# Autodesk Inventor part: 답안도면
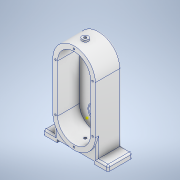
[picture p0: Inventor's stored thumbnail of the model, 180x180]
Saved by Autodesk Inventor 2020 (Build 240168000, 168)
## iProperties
Created: 2021-05
Part Number: 답안도면
Material: 알루미늄 6061
Document SubType Name: Modeling
Designer: OWner
Density: 2.7 g/cm^3
Appearance: 알루미늄 - 평지
Author: OWner
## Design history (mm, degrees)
sketch "스케치1"
  geometry: 1 further point
sketch "스케치2"
  geometry: L1 (0, 90)-(0, 0); L2 (-40, 90)-(-40, 0); L3 (40, 0)-(40, 90); A1 r 40 centre (0, 90) between (40, 90) and (-40, 90); A2 r 40 centre (0, 0) between (-40, 0) and (40, 0); 1 further point
  constraints: 8 end point, 4 point on circle, 4 tangent, 2 centre point, 1 midpoint, 1 parallel, 1 vertical
  dimensions: "d1" = 80 distance between parallel lines of L2 L3; "d2" = 45 distance of point (0, 45) L1.end
extrude "돌출1" new body sketch "스케치2" stored distance "d3" = 49; taper "d4" = 0 deg
sketch "스케치3"
  geometry: L1 (0, 0)-(0, 90); L2 (-31, 0)-(-31, 90); L3 (31, 90)-(31, 0); A1 r 31 centre (0, 0) between (-31, 0) and (31, 0); A2 r 31 centre (0, 90) between (31, 90) and (-31, 90); 1 further point
  constraints: 8 end point, 4 point on circle, 4 tangent, 2 centre point, 1 midpoint, 1 parallel, 1 vertical
  dimensions: "d5" = 45 distance of point (0, 45) L1.start; "d6" = 31 radius of A2
extrude "돌출2" cut sketch "스케치3" distance "d7" = 41; taper "d8" = 0 deg
sketch "스케치9"
  geometry: L1 (0, 0)-(0, 90); L2 (-26, 0)-(-26, 90); L3 (26, 90)-(26, 0); A1 r 26 centre (0, 0) between (-26, 0) and (26, 0); A2 r 26 centre (0, 90) between (26, 90) and (-26, 90); 1 further point
  constraints: 8 end point, 4 point on circle, 4 tangent, 2 centre point, 1 midpoint, 1 parallel, 1 vertical
  dimensions: "d34" = 45 distance of L1.start point (0, 45); "d35" = 52 distance between parallel lines of L3 L2
extrude "돌출10" join sketch "스케치9" distance "d36" = 8; taper "d37" = 0 deg
sketch "스케치10"
  geometry: C1 r 14 at (0, 90); A1 r 26 centre (0, 90) between (26, 90) and (-26, 90) reference; 1 further point
  constraints: 1 centre point, 1 coincident
  dimensions: "d38" = 28 diameter of C1
extrude "돌출11" cut sketch "스케치10" distance "d39" = 4; taper "d40" = 0 deg
sketch "스케치11"
  geometry: C1 r 14 at (0, 0) reference; C2 r 11 at (0, 0); 1 further point
  constraints: 1 centre point, 1 coincident
  dimensions: "d41" = 22 diameter of C2
extrude "돌출12" cut sketch "스케치11" distance "d42" = 4; taper "d43" = 0 deg
sketch "스케치12"
  geometry: C1 r 14 at (0, 90); C2 r 14 at (0, 0); A1 r 31 centre (0, 90) between (31, 90) and (-31, 90) reference; 1 further point
  constraints: 2 centre point, 2 coincident
  dimensions: "d44" = 28 diameter of C1; "d45" = 28 diameter of C2
extrude "돌출13" cut sketch "스케치12" distance "d46" = 8; taper "d47" = 0 deg
sketch "스케치13"
  geometry: C1 r 10 at (0, 0); 1 further point
  constraints: 1 centre point, 1 coincident
  dimensions: "d48" = 20 diameter of C1
extrude "돌출14" cut sketch "스케치13" distance "d49" = 4; taper "d50" = 0 deg
node "작업 평면1"
sketch "스케치14"
  geometry: 1 further point
sketch "스케치15"
  geometry: L1 (40, 24.5)-(-40, 24.5) reference; L2 (0, 24.5)-(0, 3.5); C1 r 6 at (0, 3.5); 2 further points
  constraints: 2 coincident, 2 end point, 1 centre point, 1 midpoint, 1 vertical
  dimensions: "d52" = 21 distance of L2.start L2.end; "d53" = 12 diameter of C1
extrude "돌출15" join sketch "스케치15" distance "d54" = 3; taper "d55" = 0 deg
sketch "스케치16"
  geometry: C1 r 6 at (0, 0); A1 r 6 centre (0, 0) between (0, 6) and (0, -6) reference; 3 further points
  constraints: 1 centre point, 1 coincident
  dimensions: "d56" = 12 diameter of C1
extrude "돌출16" join sketch "스케치16" distance "d57" = 5; taper "d58" = 0 deg
sketch "스케치17"
  geometry: C1 r 6 at (0, 0) reference; 2 further points
  constraints: 1 coincident
hole "구멍1" sketch "스케치17" at (0, 0) diameter "d59" = 4.917; stored, may be unused: countersink angle "d63" = 90 deg, drill point angle "d65" = 118 deg; dims "d60" = 12, "d61" = 4, "d62" = 2, "d64" = 29.6
sketch "스케치18"
  geometry: L1 (0, 0)-(0, 90); L2 (35, 0)-(35, 90); L3 (-35, 90)-(-35, 0); A1 r 35 centre (0, 0) between (-35, 0) and (35, 0); A2 r 35 centre (0, 90) between (35, 90) and (-35, 90); 7 further points
  constraints: 8 end point, 6 point on circle, 4 coincident, 4 tangent, 2 centre point, 1 midpoint, 1 parallel, 1 vertical
  dimensions: "d66" = 45 distance of point (0, 45) L1.start; "d67" = 35 radius of A2
hole "구멍2" sketch "스케치18" at (-35, 90), (35, 90), (0, 125), (35, 0), (0, -35), (-35, 0) diameter "d68" = 3.242; stored, may be unused: countersink angle "d72" = 90 deg, drill point angle "d74" = 118 deg; dims "d69" = 8, "d70" = 4, "d71" = 2, "d73" = 10
sketch "스케치19"
  geometry: 1 further point
node "작업 평면2"
sketch "스케치20"
  geometry: L1 (61, -24.5)-(35, -24.5); L2 (35, -24.5)-(35, 21.5); L3 (35, 21.5)-(61, 21.5); L4 (61, 21.5)-(61, -24.5); L5 (40, 24.5)-(-40, 24.5) reference; L6 (-26, -32.5)-(26, -32.5) reference; L7 (0, -32.5)-(0, 39.099); L8 (-61, -24.5)-(-35, -24.5); L9 (-35, -24.5)-(-35, 21.5); L10 (-35, 21.5)-(-61, 21.5); L11 (-61, 21.5)-(-61, -24.5); 1 further point
  constraints: 18 end point, 4 parallel, 2 horizontal, 2 perpendicular, 1 midpoint, 1 vertical, 1 other
  dimensions: "d76" = 46 distance of L3.end L1.start; "d77" = 3 distance from line of L3.end L5; "d78" = 61 distance from line of L1.start L7; "d79" = 61 distance from line of L8.start L7; "d80" = 46 distance of L10.end L8.start; "d81" = 3 distance between parallel lines of L10 L5; "d82" = 70 distance between parallel lines of L9 L2
extrude "돌출17" join sketch "스케치20" distance "d83" = 10; taper "d84" = 0 deg
sketch "스케치21"
  geometry: L1 (0, 0)-(26, 0) reference; L2 (26, 0)-(26, 5); L3 (26, 0)-(26, 10) reference; L4 (26, 5)-(96, 5); L5 (96, 0)-(96, 10) reference; L6 (21, 47)-(21, 10); L7 (0, 10)-(26, 10) reference; L8 (101, 47)-(101, 10); L9 (96, 10)-(122, 10) reference; L10 (21, 10)-(26, 10); L11 (26, 10)-(26, 5); L12 (96, 5)-(96, 10); L13 (101, 10)-(96, 10); A1 r 40 centre (61, 47) between (21, 47) and (101, 47) reference; A2 r 40 centre (61, 47) between (21, 47) and (101, 47); 1 further point
  constraints: 16 end point, 3 collinear, 2 midpoint, 2 point on circle, 2 point on line, 2 vertical, 1 centre point, 1 concentric, 1 perpendicular
  dimensions: "d85" = 5 distance of L1.end L2.end (derived)
extrude "돌출18" join sketch "스케치21" distance "d86" = 46; taper "d87" = 0 deg
sketch "스케치22"
  geometry: L1 (0, 0)-(0, 44.011); L2 (-26, 0)-(-26, 60); L3 (26, 60)-(26, 0); L4 (-26, 60)-(26, 60); L5 (26, 0)-(26, 90) reference; C1 r 11 at (0, 90) reference; A1 r 26 centre (0, 0) between (-26, 0) and (26, 0); 1 further point
  constraints: 10 end point, 2 point on circle, 2 tangent, 1 centre point, 1 coincident, 1 parallel, 1 perpendicular, 1 point on line, 1 vertical
  dimensions: "d88" = 30 vertical distance of L2.end point (0, 90)
extrude "돌출19" join sketch "스케치22" distance "d89" = 3; taper "d90" = 0 deg
sketch "스케치23"
  geometry: L1 (-25.882, -35)-(24.286, -35); L2 (-85.4, -47)-(85.4, -47) reference; L3 (0, 0)-(0, -58.606); C1 r 10 at (0, 0) reference; 1 further point
  constraints: 4 end point, 2 horizontal, 1 vertical
  dimensions: "d91" = 12 distance between parallel lines of L2 L1
sketch "스케치24"
  geometry: C1 r 2.458 at (35, 28) reference; 2 further points
  constraints: 1 coincident
hole "구멍3" sketch "스케치24" at (35, 28) diameter "d92" = 4.917; stored, may be unused: countersink angle "d96" = 90 deg, drill point angle "d98" = 118 deg; dims "d93" = 12, "d94" = 12, "d95" = 1, "d97" = 17.1
fillet "모깎기1" dims "d99" = 3
fillet "모깎기2" dims "d100" = 3
fillet "모깎기3" dims "d101" = 3
fillet "모깎기4" dims "d102" = 3
extrude "돌출20" join sketch "스케치23" distance "d103" = 1; taper "d104" = 0 deg
chamfer "모따기1" distance "d105" = 1; stored, may be unused: second distance "d106" = 2, angle "d107" = 45 deg
chamfer "모따기2" distance "d108" = 1; stored, may be unused: second distance "d109" = 2, angle "d110" = 45 deg
node "솔리드1"
feature "A9D066F2-1C7D-4E18-AEED-F7BC21143FA4" dims "d68" = 3.242, "d69" = 8, "d70" = 4, "d71" = 2, "d72" = 90 deg, "d73" = 10, "d74" = 118 deg
other parameters: "d75" = -47
